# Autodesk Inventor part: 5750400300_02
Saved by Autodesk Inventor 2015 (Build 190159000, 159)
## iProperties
Created: 2020-07
Part Number: 5750400300_02
Checked By: TraceParts S.A.
Material: Generic
Catalog Web Link: www.traceparts.com
Document SubType Name: Modeling
Designer: TraceParts
Density: 1 g/cm^3
Appearance: Default
Company: TraceParts S.A.
Author: TraceParts
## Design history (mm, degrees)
feature "5750400300_02.ipt"
body "Solid1"
